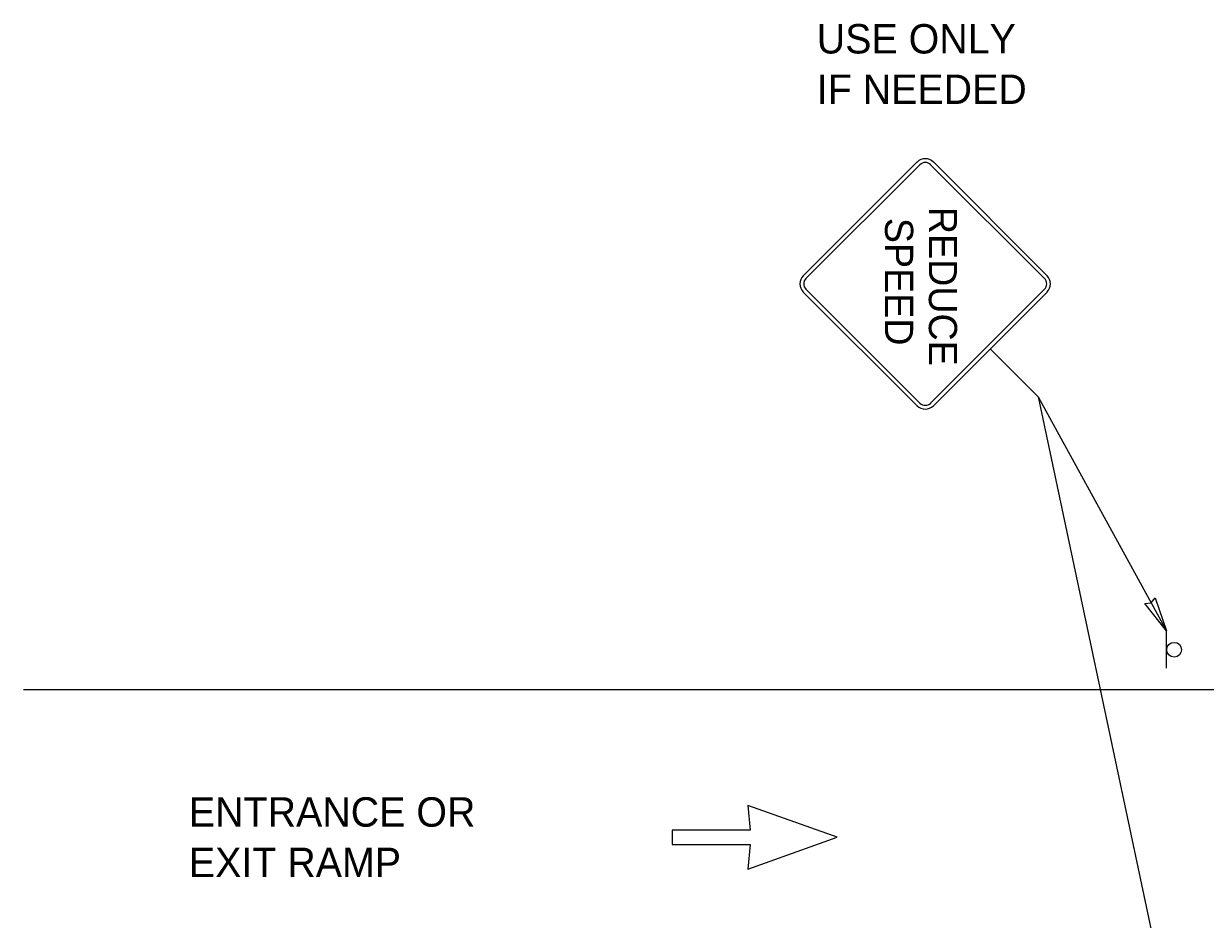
# Model space of a CAD drawing. Extents: x 46672 to 47298, y 5424 to 5829.
# Drawn here: x 46718.5 to 46830.9, y 5634.9 to 5720.1 of the extents above; entities that cross this region are included whole.
import ezdxf

# ---------------------------------------------------------------- set-up
doc = ezdxf.new("R2010")
doc.units = 0
for name, color, linetype in [('LaneDirArrow', 7, 'Continuous'), ('LeaderLine_dp', 7, 'Continuous'), ('RoadwayMisc', 7, 'Continuous'), ('SignPanel', 7, 'Continuous'), ('SignSupport', 7, 'Continuous'), ('TextLabel', 7, 'Continuous')]:
    doc.layers.add(name, color=color, linetype=linetype)

msp = doc.modelspace()

# ---------------------------------------------------------------- linework, layer by layer
at = {"layer": 'LaneDirArrow'}
for p, q in [((46795.83, 5642.7), (46787.33, 5645.71)), ((46787.33, 5645.71), (46787.58, 5643.37)), ((46787.58, 5643.37), (46780.16, 5643.36)), ((46780.16, 5643.36), (46780.16, 5641.99)), ((46787.34, 5639.66), (46795.83, 5642.7)), ((46780.16, 5641.99), (46787.58, 5642)), ((46787.58, 5642), (46787.34, 5639.66))]:
    msp.add_line(p, q, dxfattribs=at)
at = {"layer": 'LeaderLine_dp'}
for q in [(46810.4, 5689.17), (46827.16, 5627.07), (46827.16, 5662.33)]:
    msp.add_line((46814.95, 5684.62), q, dxfattribs=at)
msp.add_lwpolyline([(46827.16, 5662.33), (46825.09, 5664.94), (46825.7, 5665), (46826.1, 5665.48)], close=True, dxfattribs=at)
at = {"layer": 'RoadwayMisc'}
msp.add_line((46718.46, 5656.76), (46988.46, 5656.76), dxfattribs=at)
at = {"layer": 'SignPanel'}
for p, q in [((46803.44, 5706.96), (46792.62, 5696.13)), ((46803.7, 5706.7), (46792.87, 5695.87)), ((46815.56, 5695.87), (46804.73, 5706.7)), ((46815.82, 5696.13), (46804.99, 5706.96)), ((46792.62, 5694.58), (46803.44, 5683.75)), ((46792.87, 5694.84), (46803.7, 5684.01)), ((46804.73, 5684.01), (46815.56, 5694.84)), ((46804.99, 5683.75), (46815.82, 5694.58))]:
    msp.add_line(p, q, dxfattribs=at)
for centre, radius, start, end in [((46804.22, 5706.18), 1.09, 45, 135), ((46804.22, 5706.18), 0.729, 45, 135), ((46793.39, 5695.36), 1.09, 135, 225), ((46793.39, 5695.36), 0.729, 135, 225), ((46815.04, 5695.36), 0.729, 315, 45), ((46815.04, 5695.36), 1.09, 315, 45), ((46804.22, 5684.53), 0.729, 225, 315), ((46804.22, 5684.53), 1.09, 225, 315)]:
    msp.add_arc(centre, radius, start, end, dxfattribs=at)
at = {"layer": 'SignSupport'}
msp.add_line((46827.16, 5658.78), (46827.16, 5662.33), dxfattribs=at)
msp.add_circle((46827.89, 5660.54), 0.703, dxfattribs=at)

# ---------------------------------------------------------------- texts
at = {"layer": 'SignPanel'}
for s, p in [('REDUCE', (46804.56, 5702.69)), ('SPEED', (46800.39, 5701.64))]:
    msp.add_text(s, height=2.68, rotation=270, dxfattribs=at).set_placement(p)
at = {"layer": 'TextLabel'}
for s, p in [('USE ONLY', (46793.9, 5717.28)), ('IF NEEDED', (46793.9, 5712.48)), ('ENTRANCE OR ', (46734.18, 5643.7)), ('EXIT RAMP', (46734.18, 5638.9))]:
    msp.add_text(s, height=2.8, dxfattribs=at).set_placement(p)

doc.saveas('drawing.dxf')
